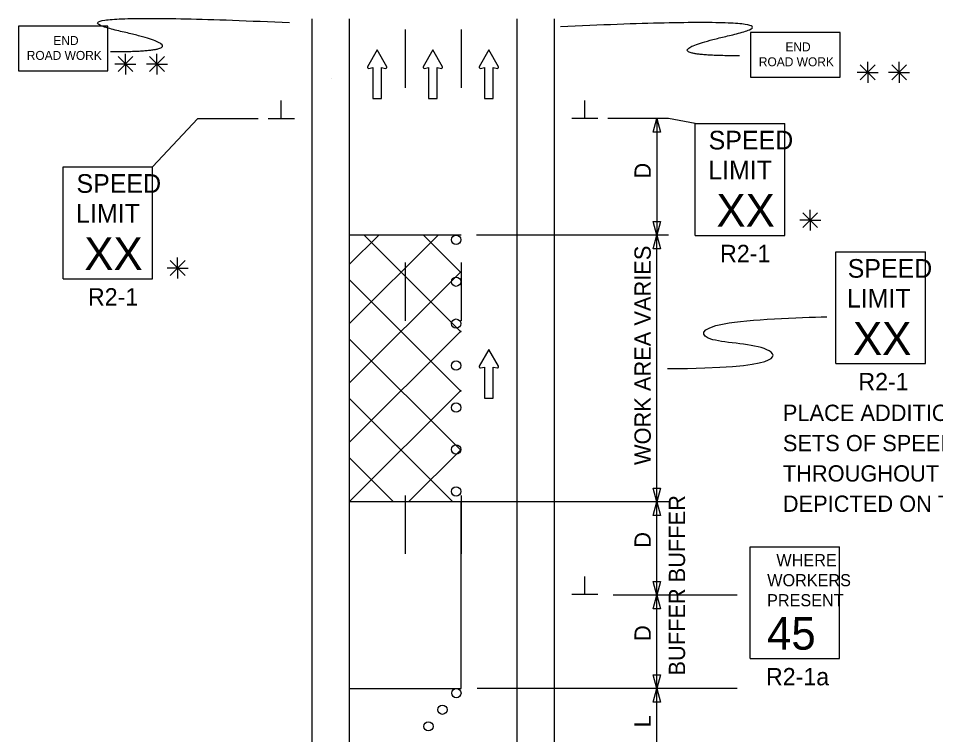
# Model space of a CAD drawing. Extents: x 16590 to 19504, y 5703 to 6974.
# Drawn here: x 17775 to 18168.7, y 6618.1 to 6925.5 of the extents above; entities that cross this region are included whole.
import ezdxf

# ---------------------------------------------------------------- set-up
doc = ezdxf.new("R2010")
doc.units = 0
for name, color, linetype in [('ALI_LEGAL_EX', 7, 'Continuous'), ('BORDER', 7, 'Continuous'), ('MT_SCRATCH_LEVEL_A', 7, 'Continuous'), ('MT_SCRATCH_LEVEL_E', 7, 'Continuous'), ('PAVT_EDGE_EX', 7, 'Continuous'), ('TRAFFIC_SIGNS_PR', 7, 'Continuous'), ('TYPICAL_TEXT_DIMEN_PR', 7, 'Continuous')]:
    doc.layers.add(name, color=color, linetype=linetype)

msp = doc.modelspace()

# ---------------------------------------------------------------- linework, layer by layer
at = {"layer": 'ALI_LEGAL_EX'}
for points in [[(17940.96, 6920.69), (17940.96, 6895.69)], [(17964.96, 6920.69), (17964.96, 6895.69)], [(17940.96, 6820.69), (17940.96, 6795.69)], [(17964.96, 6820.69), (17964.96, 6795.69)], [(17940.96, 6720.69), (17940.96, 6695.69)], [(17964.96, 6720.69), (17964.96, 6695.69)]]:
    msp.add_lwpolyline(points, dxfattribs=at)
at = {"layer": 'BORDER'}
msp.add_line((17909.54, 6899.78), (17909.54, 6899.78), dxfattribs=at)
at = {"layer": 'MT_SCRATCH_LEVEL_A'}
for p, q in [((17964.96, 6832.5), (17916.96, 6832.5)), ((17964.96, 6717.96), (17916.96, 6717.96))]:
    msp.add_line(p, q, dxfattribs=at)
at = {"layer": 'MT_SCRATCH_LEVEL_E'}
for p, q in [((17928.96, 6911.94), (17924.85, 6904.69)), ((17933.1, 6904.69), (17928.96, 6911.94)), ((17952.86, 6911.94), (17948.75, 6904.69)), ((17957.01, 6904.69), (17952.86, 6911.94)), ((17976.91, 6911.94), (17972.8, 6904.69)), ((17981.06, 6904.69), (17976.91, 6911.94)), ((17925.33, 6904.01), (17927.1, 6904.32)), ((17927.1, 6904.32), (17927.1, 6891.07)), ((17930.85, 6891.07), (17930.85, 6904.32)), ((17930.85, 6904.32), (17932.62, 6904.01)), ((17949.23, 6904.01), (17951.01, 6904.32)), ((17951.01, 6904.32), (17951.01, 6891.07)), ((17954.75, 6891.07), (17954.75, 6904.32)), ((17954.75, 6904.32), (17956.53, 6904.01)), ((17973.28, 6904.01), (17975.06, 6904.32)), ((17975.06, 6904.32), (17975.06, 6891.07)), ((17978.8, 6891.07), (17978.8, 6904.32)), ((17978.8, 6904.32), (17980.58, 6904.01)), ((17927.1, 6891.07), (17930.85, 6891.07)), ((17951.01, 6891.07), (17954.75, 6891.07)), ((17975.06, 6891.07), (17978.8, 6891.07)), ((17976.91, 6783.4), (17972.8, 6776.16)), ((17981.06, 6776.16), (17976.91, 6783.4)), ((17973.28, 6775.48), (17975.06, 6775.79)), ((17975.06, 6775.79), (17975.06, 6762.53)), ((17978.8, 6762.53), (17978.8, 6775.79)), ((17978.8, 6775.79), (17980.58, 6775.48)), ((17975.06, 6762.53), (17978.8, 6762.53))]:
    msp.add_line(p, q, dxfattribs=at)
for centre, start, end in [((17925.25, 6904.47), 150.4248, 279.9638), ((17932.69, 6904.47), 260.0362, 29.7731), ((17949.16, 6904.47), 150.4248, 279.9638), ((17956.6, 6904.47), 260.0362, 29.7731), ((17973.21, 6904.47), 150.4248, 279.9638), ((17980.65, 6904.47), 260.0362, 29.7731), ((17973.21, 6775.94), 150.4248, 279.9638), ((17980.65, 6775.94), 260.0362, 29.7731)]:
    msp.add_arc(centre, 0.463, start, end, dxfattribs=at)
at = {"layer": 'PAVT_EDGE_EX'}
for p, q in [((17900.96, 6925.33), (17900.96, 6504.84)), ((17916.96, 6925.33), (17916.96, 6504.84)), ((17988.96, 6925.33), (17988.96, 6504.84)), ((18004.96, 6925.33), (18004.96, 6504.84)), ((17964.96, 6832.5), (17916.96, 6832.5)), ((17916.96, 6832.5), (17916.96, 6717.96)), ((17916.96, 6819.79), (17929.67, 6832.5)), ((17916.96, 6794.33), (17955.12, 6832.5)), ((17964.96, 6790.88), (17923.34, 6832.5)), ((17964.96, 6816.34), (17948.79, 6832.5)), ((17916.96, 6768.88), (17964.96, 6816.88)), ((17964.96, 6765.42), (17916.96, 6813.42)), ((17916.96, 6743.42), (17964.96, 6791.42)), ((17964.96, 6739.97), (17916.96, 6787.97)), ((17916.96, 6717.96), (17964.96, 6765.96)), ((17961.51, 6717.96), (17916.96, 6762.51)), ((17942.41, 6717.96), (17964.96, 6740.51)), ((17936.05, 6717.96), (17916.96, 6737.06))]:
    msp.add_line(p, q, dxfattribs=at)
msp.add_lwpolyline([(17964.96, 6717.96), (17916.96, 6717.96), (17916.96, 6637.96), (17964.96, 6637.96)], close=True, dxfattribs=at)
at = {"layer": 'TRAFFIC_SIGNS_PR'}
for p, q in [((18065.45, 6880.37), (18103.9, 6880.37)), ((18065.45, 6832.31), (18065.45, 6880.37)), ((18103.9, 6832.31), (18103.9, 6880.37)), ((17794.15, 6861.76), (17832.6, 6861.76)), ((17794.15, 6813.7), (17794.15, 6861.76)), ((17832.6, 6813.7), (17832.6, 6861.76)), ((18065.45, 6832.31), (18103.9, 6832.31)), ((18125.89, 6825.32), (18164.29, 6825.32)), ((18125.89, 6777.32), (18125.89, 6825.32)), ((18164.29, 6777.32), (18164.29, 6825.32)), ((17794.15, 6813.7), (17832.6, 6813.7)), ((18125.89, 6777.32), (18164.29, 6777.32)), ((18089, 6698.72), (18127.4, 6698.72)), ((18089, 6650.72), (18089, 6698.72)), ((18127.4, 6650.72), (18127.4, 6698.72)), ((18089, 6650.72), (18127.4, 6650.72))]:
    msp.add_line(p, q, dxfattribs=at)
for points in [[(17774.97, 6902.91), (17813.42, 6902.91), (17813.42, 6922.13), (17774.97, 6922.13)], [(18089.17, 6900.17), (18127.62, 6900.17), (18127.62, 6919.4), (18089.17, 6919.4)]]:
    msp.add_lwpolyline(points, close=True, dxfattribs=at)
for centre in [(17962.86, 6830.48), (17962.86, 6812.48), (17962.86, 6794.48), (17962.86, 6776.48), (17962.86, 6758.48), (17962.86, 6740.48), (17962.86, 6722.48), (17962.96, 6635.96), (17956.96, 6628.82), (17950.96, 6621.68)]:
    msp.add_circle(centre, 2, dxfattribs=at)
for points in [[(17814.53, 6911.21), (17857.04, 6911.21), (17780.52, 6928.63), (17891.31, 6923.69)], [(18084.45, 6909.4), (18041.94, 6909.4), (18118.46, 6926.82), (18007.67, 6921.88)]]:
    msp.add_open_spline(points, degree=2, dxfattribs=at)
at = {"layer": 'TYPICAL_TEXT_DIMEN_PR'}
for p, q in [((17820.96, 6905.85), (17820.96, 6910.31)), ((17834.47, 6905.85), (17834.47, 6910.31)), ((17820.96, 6905.85), (17816.43, 6905.85)), ((17817.78, 6909.04), (17824.15, 6902.66)), ((17824.15, 6909.04), (17817.78, 6902.66)), ((17820.96, 6905.85), (17824.15, 6905.85)), ((17820.96, 6905.85), (17825.44, 6905.85)), ((17820.96, 6905.85), (17820.96, 6901.35)), ((17834.47, 6905.85), (17829.94, 6905.85)), ((17831.28, 6909.04), (17837.66, 6902.66)), ((17837.66, 6909.04), (17831.28, 6902.66)), ((17834.47, 6905.85), (17837.66, 6905.85)), ((17834.47, 6905.85), (17838.95, 6905.85)), ((17834.47, 6905.85), (17834.47, 6901.35)), ((18136.32, 6905.49), (18142.69, 6899.11)), ((18142.69, 6905.49), (18136.32, 6899.11)), ((18139.51, 6902.3), (18139.51, 6906.75)), ((18156.2, 6905.49), (18149.82, 6899.11)), ((18149.83, 6905.49), (18156.2, 6899.11)), ((18153.01, 6902.3), (18153.01, 6906.75)), ((18139.51, 6902.3), (18134.97, 6902.3)), ((18139.51, 6902.3), (18142.69, 6902.3)), ((18139.51, 6902.3), (18143.98, 6902.3)), ((18139.51, 6902.3), (18139.51, 6897.8)), ((18153.01, 6902.3), (18148.48, 6902.3)), ((18153.01, 6902.3), (18156.2, 6902.3)), ((18153.01, 6902.3), (18157.49, 6902.3)), ((18153.01, 6902.3), (18153.01, 6897.8)), ((17887.83, 6882.5), (17887.83, 6890.28)), ((18018.08, 6882.5), (18018.08, 6890.28)), ((17832.6, 6861.76), (17851.96, 6882.5)), ((17851.96, 6882.5), (17877.96, 6882.5)), ((17882.21, 6882.5), (17893.46, 6882.5)), ((18023.71, 6882.5), (18012.46, 6882.5)), ((18053.96, 6882.5), (18027.96, 6882.5)), ((18047.39, 6876.64), (18048.96, 6882.5)), ((18048.96, 6882.5), (18048.96, 6832.5)), ((18048.96, 6882.5), (18050.53, 6876.64)), ((18065.45, 6880.37), (18053.96, 6882.5)), ((18048.96, 6876.64), (18047.39, 6876.64)), ((18050.53, 6876.64), (18048.96, 6876.64)), ((18114.85, 6838.9), (18114.85, 6843.36)), ((18114.85, 6838.9), (18110.31, 6838.9)), ((18111.66, 6842.09), (18118.03, 6835.72)), ((18118.03, 6842.09), (18111.66, 6835.72)), ((18114.85, 6838.9), (18118.03, 6838.9)), ((18114.85, 6838.9), (18119.32, 6838.9)), ((18114.85, 6838.9), (18114.85, 6834.4)), ((18048.96, 6832.5), (18047.39, 6838.36)), ((18047.39, 6838.36), (18048.96, 6838.36)), ((18048.96, 6838.36), (18050.53, 6838.36)), ((18050.53, 6838.36), (18048.96, 6832.5)), ((18053.96, 6832.5), (17971.56, 6832.5)), ((18047.39, 6826.64), (18048.96, 6832.5)), ((18048.96, 6717.96), (18048.96, 6832.5)), ((18048.96, 6832.5), (18050.53, 6826.64)), ((18048.96, 6826.64), (18047.39, 6826.64)), ((18050.53, 6826.64), (18048.96, 6826.64)), ((17840.12, 6821.53), (17846.5, 6815.16)), ((17846.5, 6821.53), (17840.12, 6815.16)), ((17843.31, 6818.34), (17843.31, 6822.8)), ((17843.31, 6818.34), (17838.78, 6818.34)), ((17843.31, 6818.34), (17846.5, 6818.34)), ((17843.31, 6818.34), (17847.79, 6818.34)), ((17843.31, 6818.34), (17843.31, 6813.84)), ((18048.96, 6717.96), (18047.39, 6723.83)), ((18047.39, 6723.83), (18048.96, 6723.83)), ((18048.96, 6723.83), (18050.53, 6723.83)), ((18050.53, 6723.83), (18048.96, 6717.96)), ((18053.96, 6717.96), (17964.96, 6717.96)), ((18047.39, 6712.1), (18048.96, 6717.96)), ((18048.96, 6677.96), (18048.96, 6717.96)), ((18048.96, 6717.96), (18050.53, 6712.1)), ((18048.96, 6712.1), (18047.39, 6712.1)), ((18050.53, 6712.1), (18048.96, 6712.1)), ((18018.08, 6678.18), (18018.08, 6685.97)), ((18048.96, 6677.96), (18047.39, 6683.83)), ((18047.39, 6683.83), (18048.96, 6683.83)), ((18048.96, 6683.83), (18050.53, 6683.83)), ((18050.53, 6683.83), (18048.96, 6677.96)), ((18023.71, 6678.18), (18012.46, 6678.18)), ((18083.55, 6677.96), (18030.26, 6677.96)), ((18047.39, 6672.1), (18048.96, 6677.96)), ((18048.96, 6677.96), (18050.53, 6672.1)), ((18048.96, 6637.96), (18048.96, 6677.96)), ((18048.96, 6672.1), (18047.39, 6672.1)), ((18050.53, 6672.1), (18048.96, 6672.1)), ((18048.96, 6637.96), (18047.39, 6643.83)), ((18047.39, 6643.83), (18048.96, 6643.83)), ((18048.96, 6643.83), (18050.53, 6643.83)), ((18050.53, 6643.83), (18048.96, 6637.96)), ((18083.55, 6637.96), (17971.92, 6637.96)), ((18047.39, 6632.1), (18048.96, 6637.96)), ((18048.96, 6607.4), (18048.96, 6637.96)), ((18048.96, 6637.96), (18050.53, 6632.1)), ((18048.96, 6632.1), (18047.39, 6632.1)), ((18050.53, 6632.1), (18048.96, 6632.1))]:
    msp.add_line(p, q, dxfattribs=at)
msp.add_open_spline([(18053.61, 6775.23), (18102.08, 6775.23), (18102.08, 6785.99), (18067.16, 6785.99), (18067.16, 6795.65), (18110.02, 6797.17), (18121.93, 6797.43)], degree=3, dxfattribs=at)

# ---------------------------------------------------------------- texts
at = {"layer": 'TRAFFIC_SIGNS_PR'}
for s, height, p in [('END', 3.836, (17789.99, 6914.05)), ('END', 3.836, (18104.19, 6911.32)), ('ROAD WORK', 3.836, (17778.58, 6907.66)), ('ROAD WORK', 3.836, (18092.78, 6904.92)), ('SPEED', 8.01, (18071.23, 6869.22)), ('LIMIT', 8.01, (18071.07, 6856.4)), ('SPEED', 8.01, (17799.93, 6850.61)), ('XX', 14.048, (18074.58, 6836.07)), ('LIMIT', 8.01, (17799.76, 6837.79)), ('XX', 14.048, (17803.28, 6817.46)), ('R2-1', 7.449, (18076.14, 6820.85)), ('SPEED', 8, (18130.92, 6814.18)), ('R2-1', 7.449, (17804.84, 6802.24)), ('LIMIT', 8, (18130.59, 6801.38)), ('XX', 14.031, (18133.19, 6781.08)), ('R2-1', 7.44, (18135.5, 6765.88)), ('PLACE ADDITIONAL SUPPLEMENTAL', 7, (18103.08, 6752.71)), ('SETS OF SPEED LIMIT SIGNS', 7, (18103.08, 6739.71)), ('THROUGHOUT THE WORK AREA AS', 7, (18103.08, 6726.71)), ('DEPICTED ON TYPICAL M0100a.', 7, (18103.08, 6713.71)), ('WHERE', 5.2, (18100.31, 6690.4)), ('WORKERS', 5.2, (18096.38, 6681.8)), ('PRESENT', 5.2, (18096.32, 6673.2)), ('45', 14.031, (18096.31, 6654.57)), ('R2-1a', 7.44, (18095.85, 6639.28))]:
    msp.add_text(s, height=height, dxfattribs=at).set_placement(p)
at = {"layer": 'TYPICAL_TEXT_DIMEN_PR'}
for s, p in [('D', (18046.4, 6856.72)), ('WORK AREA VARIES', (18046.4, 6733.81)), ('BUFFER', (18061.12, 6683.47)), ('D', (18046.4, 6698.3)), ('BUFFER', (18061.12, 6643.47)), ('D', (18046.4, 6658.3)), ('L', (18046.4, 6621.26))]:
    msp.add_text(s, height=7, rotation=90, dxfattribs=at).set_placement(p)

doc.saveas('drawing.dxf')
